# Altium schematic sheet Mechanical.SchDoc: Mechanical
size A4; SheetNumber: 7; SheetTotal: 8
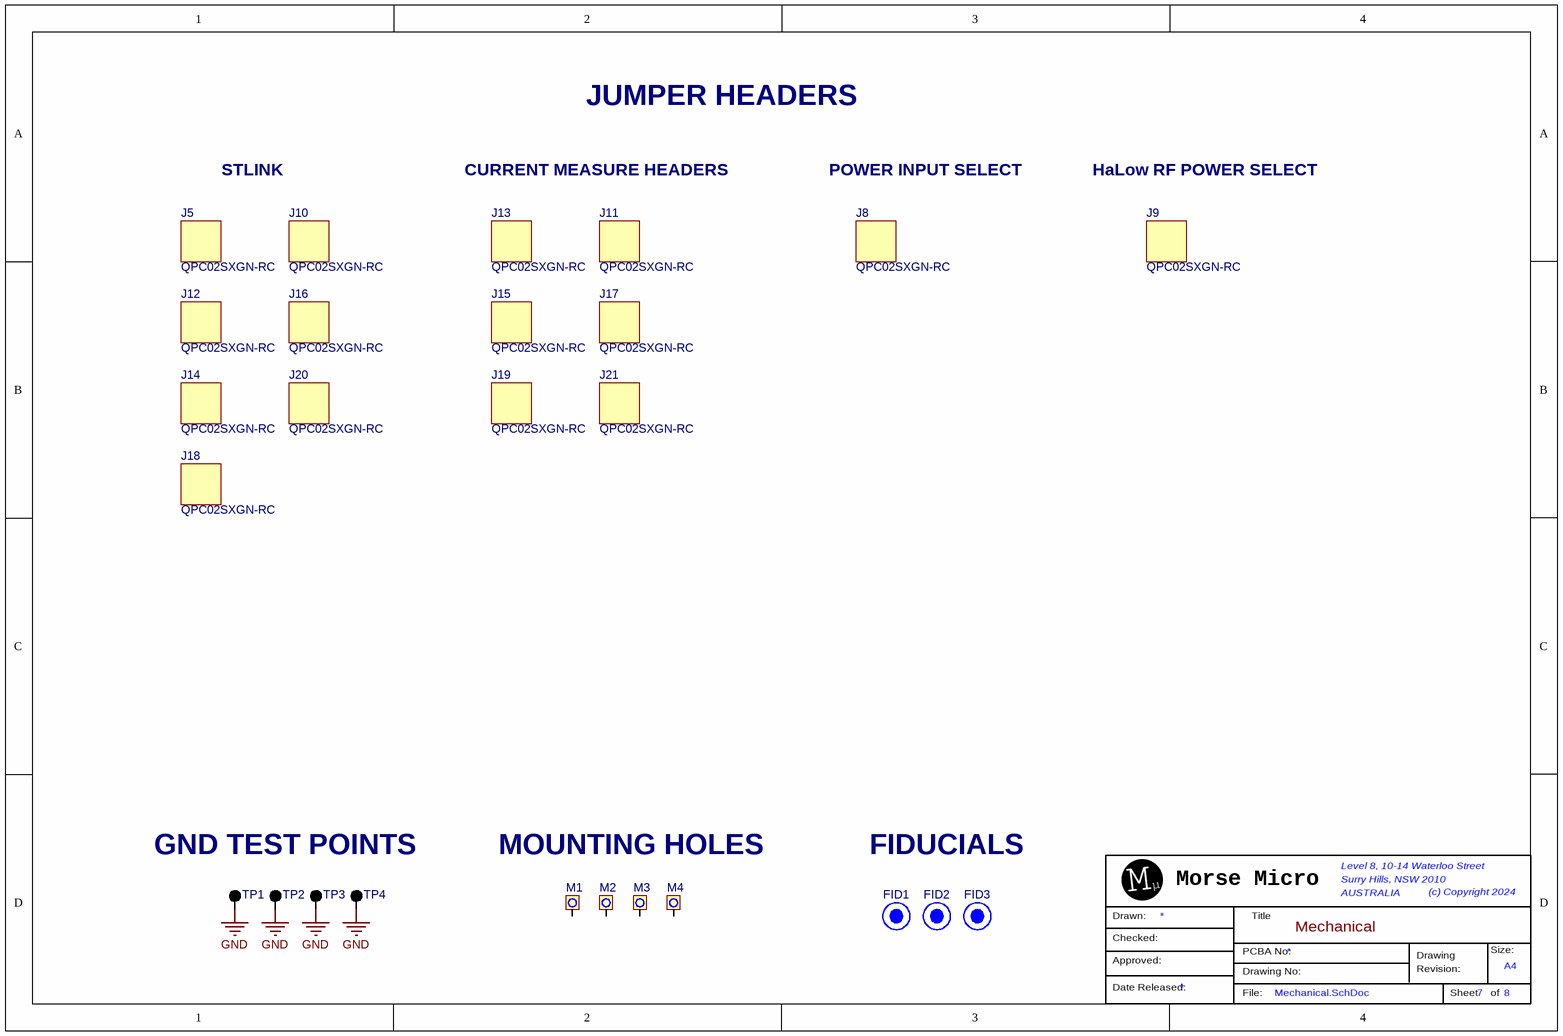
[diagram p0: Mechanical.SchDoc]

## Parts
FID1  PAD0002  [FIDUCIAL_1MM]  (value not drawn)  (no BOM)
FID2  PAD0002  [FIDUCIAL_1MM]  (value not drawn)  (no BOM)
FID3  PAD0002  [FIDUCIAL_1MM]  (value not drawn)  (no BOM)
J5  QPC02SXGN-RC  [FP-QPC02SXGN-RC-MFG]
J8  QPC02SXGN-RC  [FP-QPC02SXGN-RC-MFG]
J9  QPC02SXGN-RC  [FP-QPC02SXGN-RC-MFG]
J10  QPC02SXGN-RC  [FP-QPC02SXGN-RC-MFG]
J11  QPC02SXGN-RC  [FP-QPC02SXGN-RC-MFG]
J12  QPC02SXGN-RC  [FP-QPC02SXGN-RC-MFG]
J13  QPC02SXGN-RC  [FP-QPC02SXGN-RC-MFG]
J14  QPC02SXGN-RC  [FP-QPC02SXGN-RC-MFG]
J15  QPC02SXGN-RC  [FP-QPC02SXGN-RC-MFG]
J16  QPC02SXGN-RC  [FP-QPC02SXGN-RC-MFG]
J17  QPC02SXGN-RC  [FP-QPC02SXGN-RC-MFG]
J18  QPC02SXGN-RC  [FP-QPC02SXGN-RC-MFG]
J19  QPC02SXGN-RC  [FP-QPC02SXGN-RC-MFG]
J20  QPC02SXGN-RC  [FP-QPC02SXGN-RC-MFG]
J21  QPC02SXGN-RC  [FP-QPC02SXGN-RC-MFG]
M1  MH_300_275_NPTH  [MH_300_275_NPTH]  (value not drawn)  (no BOM)
M2  MH_300_275_NPTH  [MH_300_275_NPTH]  (value not drawn)  (no BOM)
M3  MH_300_275_NPTH  [MH_300_275_NPTH]  (value not drawn)  (no BOM)
M4  MH_300_275_NPTH  [MH_300_275_NPTH]  (value not drawn)  (no BOM)
TP1  TP-BLK  [FP-5001-MFG]  (value not drawn)
TP2  TP-BLK  [FP-5001-MFG]  (value not drawn)
TP3  TP-BLK  [FP-5001-MFG]  (value not drawn)
TP4  TP-BLK  [FP-5001-MFG]  (value not drawn)

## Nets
GND: TP1.1 TP2.1 TP3.1 TP4.1

Not connected (* = marked no-connect by the designer): M1 1; M2 1; M3 1; M4 1

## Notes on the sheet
- JUMPER HEADERS
- STLINK
- CURRENT MEASURE HEADERS
- POWER INPUT SELECT
- HaLow RF POWER SELECT
- GND TEST POINTS
- MOUNTING HOLES
- FIDUCIALS

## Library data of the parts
FID1-FID3 = PAD0002-2: 1mm Round Fiducial, 0.5mm Space
J5 J8-J21 = CMP-00006-6: Shunts/Jumper Connector; Manufacturer Series: QPC; Body Breadth: 0.097inch; Contact Pattern: RECTANGULAR; Body Depth: 0.235inch; Number Of Connectors: 1; Contact Style: SQ PIN-SKT; Body Length: 0.197inch; Polarization Key: POLARIZED HOUSING; Reliability: COMMERCIAL; Reference Standard: UL; Mounting Option 1: LOCKING; Rated Current (Signal): 3A; Mating Contact Pitch: 0.1inch
M1-M4 = PAD0031: MH NPTH 3.00mm DIA 2.75mm HOLE
TP1-TP4 = TPN0006-3: Test Point PCB, Black 0.040"D; Value: Black Color; Generic Allowed: Yes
